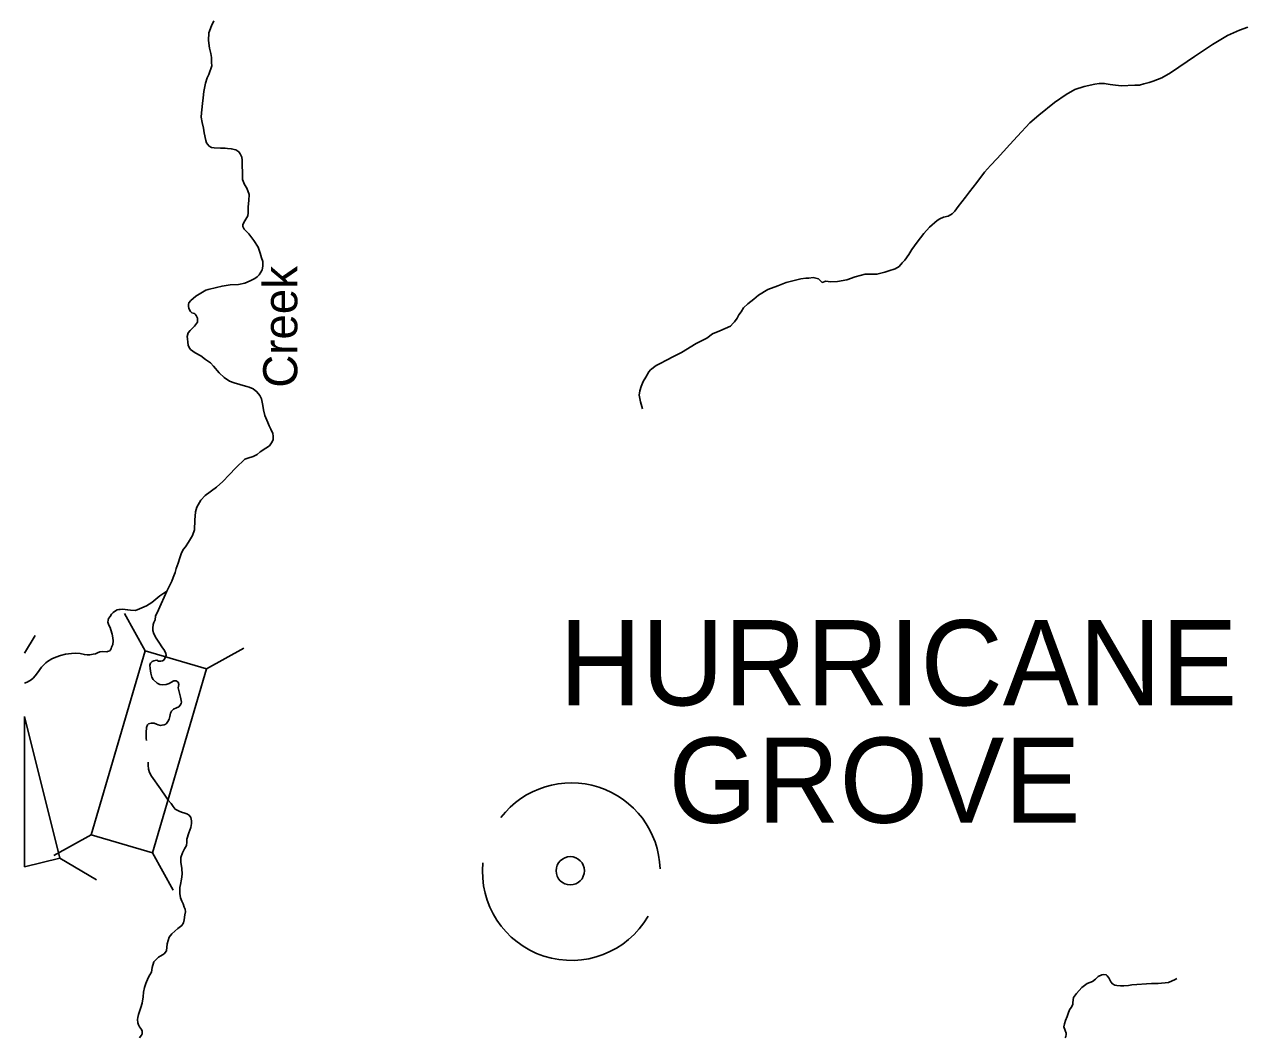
# Model space of a CAD drawing. Extents: x -492261 to -432772, y 1441225 to 1452922.
# Drawn here: x -461914.6 to -461726, y 1451913.8 to 1452070.7 of the extents above; entities that cross this region are included whole.
import ezdxf

# ---------------------------------------------------------------- set-up
doc = ezdxf.new("R2010")
doc.units = 0
doc.layers.add('Default', color=7, linetype='Continuous')

msp = doc.modelspace()

# ---------------------------------------------------------------- linework, layer by layer
at = {"layer": 'Default'}
for p, q in [((-461895.87, 1451973.72), (-461899.04, 1451979.51)), ((-461914.56, 1451973.33), (-461912.9, 1451976.1)), ((-461886.37, 1451970.94), (-461880.58, 1451974.11)), ((-461914.56, 1451963.53), (-461914.56, 1451940.25)), ((-461909.05, 1451941.63), (-461914.56, 1451963.53)), ((-461904.21, 1451945.22), (-461910, 1451942.05)), ((-461914.56, 1451940.25), (-461909.05, 1451941.63)), ((-461909.05, 1451941.63), (-461903.39, 1451938.24)), ((-461894.71, 1451942.44), (-461891.54, 1451936.65))]:
    msp.add_line(p, q, dxfattribs=at)
for points in [[(-461885.25, 1452071.25), (-461885.62, 1452070.49), (-461886.01, 1452069.39), (-461886.08, 1452068.21), (-461885.92, 1452067.04), (-461885.72, 1452066.21), (-461885.62, 1452065.56), (-461885.59, 1452064.79), (-461885.53, 1452064.28), (-461886, 1452062.96), (-461886.25, 1452062.43), (-461886.54, 1452061.63), (-461886.79, 1452060.32), (-461886.91, 1452059.35), (-461886.98, 1452058.47), (-461887.1, 1452057.49), (-461887.17, 1452057.02), (-461887.19, 1452056.34), (-461887.04, 1452055.52), (-461886.86, 1452054.62), (-461886.73, 1452053.92), (-461886.65, 1452053.44), (-461886.6, 1452053.19), (-461886.5, 1452052.74), (-461886.37, 1452052.39), (-461886.22, 1452052.14), (-461885.94, 1452051.84), (-461885.62, 1452051.67), (-461885.19, 1452051.6), (-461884.2, 1452051.55), (-461883.47, 1452051.53), (-461883.12, 1452051.51), (-461882.55, 1452051.44), (-461881.85, 1452051.27), (-461881.35, 1452050.97), (-461881.15, 1452050.67), (-461880.92, 1452050.17), (-461880.87, 1452049.67), (-461880.84, 1452048.97), (-461880.81, 1452047.67), (-461880.78, 1452046.67), (-461880.5, 1452045.94), (-461880.12, 1452045.37), (-461879.77, 1452044.39), (-461879.84, 1452043.42), (-461879.93, 1452042.47), (-461879.93, 1452041.87), (-461879.95, 1452041.51), (-461880, 1452041.06), (-461880.42, 1452040.31), (-461880.74, 1452039.73), (-461880.74, 1452039.43), (-461880.54, 1452038.98), (-461879.81, 1452038.26), (-461879.03, 1452037.24), (-461878.4, 1452036.22), (-461878.05, 1452035.29), (-461877.84, 1452034.57), (-461877.67, 1452033.99), (-461877.64, 1452033.39), (-461877.71, 1452032.89), (-461877.76, 1452032.72), (-461877.96, 1452032.32), (-461878.23, 1452031.94), (-461878.53, 1452031.61), (-461878.9, 1452031.36)], [(-461725.21, 1452070.26), (-461726.53, 1452069.83), (-461728.38, 1452068.98), (-461730.69, 1452067.61), (-461733.49, 1452065.73), (-461734.63, 1452064.96), (-461737.18, 1452063.21), (-461738.53, 1452062.44), (-461739.89, 1452061.94), (-461740.49, 1452061.72), (-461741.33, 1452061.48), (-461742, 1452061.32), (-461742.73, 1452061.29), (-461744.84, 1452061.19), (-461746.1, 1452061.34), (-461746.56, 1452061.4), (-461747.45, 1452061.57), (-461748.26, 1452061.54), (-461748.89, 1452061.47), (-461750.58, 1452061.09), (-461752.02, 1452060.61), (-461753.37, 1452059.86), (-461755.14, 1452058.62), (-461757.6, 1452056.64), (-461758.99, 1452055.47), (-461760.89, 1452053.41), (-461762.08, 1452052.12), (-461764, 1452049.92), (-461765.08, 1452048.85), (-461765.96, 1452047.82), (-461767.18, 1452046.21), (-461768.31, 1452044.77), (-461768.93, 1452043.97), (-461770.08, 1452042.49), (-461770.57, 1452041.81), (-461770.99, 1452041.35), (-461771.59, 1452041), (-461772.34, 1452040.85), (-461772.92, 1452040.59), (-461773.32, 1452040.33), (-461774.5, 1452039.31), (-461775.36, 1452038.33), (-461776.41, 1452037), (-461777.22, 1452035.84), (-461777.67, 1452035.06), (-461778.32, 1452034.21), (-461778.74, 1452033.77), (-461779.19, 1452033.24), (-461779.79, 1452032.85), (-461780.81, 1452032.55), (-461781.4, 1452032.35), (-461782.63, 1452032.02), (-461784.45, 1452032.01), (-461786, 1452031.61), (-461787.29, 1452031.18), (-461788.75, 1452030.9), (-461789.82, 1452030.87), (-461790.53, 1452030.96), (-461791.12, 1452030.76), (-461791.69, 1452031.3), (-461792.51, 1452031.5), (-461793.18, 1452031.44), (-461793.62, 1452031.44), (-461794.39, 1452031.3), (-461796.69, 1452030.74), (-461797.94, 1452030.25), (-461799.5, 1452029.68), (-461800.94, 1452028.8), (-461801.68, 1452028.14), (-461802.62, 1452027.42), (-461803.26, 1452026.82), (-461803.65, 1452026.21), (-461804.02, 1452025.72), (-461804.28, 1452025.24), (-461804.65, 1452024.65), (-461804.88, 1452024.44), (-461805.31, 1452023.99), (-461806.92, 1452023.26), (-461808.08, 1452022.78), (-461808.95, 1452022.14), (-461810.62, 1452021.3), (-461812.88, 1452019.93), (-461814.19, 1452019.26), (-461815.11, 1452018.77), (-461816.27, 1452018.16), (-461816.77, 1452017.88), (-461817.66, 1452017.2), (-461817.95, 1452016.93), (-461818.4, 1452016.08), (-461818.81, 1452015.39), (-461819.11, 1452014.63), (-461819.31, 1452013.98), (-461819.41, 1452013.29)], [(-461878.9, 1452031.36), (-461879.2, 1452031.21), (-461879.6, 1452030.98), (-461880.42, 1452030.62), (-461881.42, 1452030.44), (-461882.69, 1452030.36), (-461883.96, 1452030.2), (-461884.83, 1452029.97), (-461886.13, 1452029.66), (-461886.45, 1452029.56), (-461888.04, 1452028.63), (-461888.79, 1452027.95), (-461889.09, 1452027.59), (-461889.16, 1452027.34), (-461889.18, 1452027.09), (-461889.13, 1452026.72), (-461888.85, 1452026.24), (-461888.63, 1452026.07), (-461888.25, 1452025.95), (-461888.1, 1452025.85), (-461887.95, 1452025.65), (-461887.78, 1452025.22), (-461887.77, 1452024.62), (-461888.22, 1452023.99), (-461888.57, 1452023.64), (-461888.91, 1452023.32), (-461889.21, 1452022.94), (-461889.36, 1452022.36), (-461889.31, 1452022.01), (-461889.25, 1452021.51), (-461889.23, 1452021.06), (-461889.07, 1452020.66), (-461888.85, 1452020.39), (-461888.1, 1452019.87), (-461887.27, 1452019.37), (-461886.52, 1452018.82), (-461885.77, 1452018.3), (-461885.27, 1452017.8), (-461884.41, 1452016.78), (-461883.66, 1452016.06), (-461882.81, 1452015.49), (-461882.11, 1452015.2), (-461881.23, 1452014.95), (-461880.69, 1452014.8), (-461880.11, 1452014.63), (-461879.79, 1452014.53), (-461879.14, 1452014.26), (-461878.56, 1452013.84), (-461878.11, 1452013.24), (-461877.88, 1452012.72), (-461877.65, 1452011.69), (-461877.55, 1452011.04), (-461877.34, 1452010.17), (-461876.89, 1452009.09), (-461876.66, 1452008.57), (-461876.43, 1452008.04), (-461876.13, 1452007.35), (-461876.05, 1452006.97), (-461876.08, 1452006.39), (-461876.3, 1452005.92), (-461876.62, 1452005.47), (-461877.17, 1452005.11), (-461878.06, 1452004.53), (-461878.51, 1452004.13), (-461879.16, 1452003.82), (-461879.98, 1452003.57), (-461880.45, 1452003.39), (-461881.84, 1452002.06), (-461882.88, 1452000.95), (-461883.85, 1451999.94), (-461884.84, 1451999.08), (-461886.58, 1451997.77), (-461887.25, 1451997.04), (-461887.87, 1451995.96), (-461888.09, 1451995.24), (-461888.19, 1451993.96), (-461888.25, 1451992.46), (-461888.55, 1451991.55), (-461889.14, 1451990.52), (-461889.61, 1451989.82), (-461889.91, 1451989.47), (-461890.23, 1451988.87), (-461890.5, 1451988.11), (-461890.77, 1451987.29), (-461891.04, 1451986.46), (-461891.24, 1451985.86), (-461891.51, 1451985.08), (-461891.73, 1451984.5), (-461891.98, 1451983.97), (-461892.5, 1451982.94), (-461893.78, 1451980.08), (-461894.25, 1451979.08), (-461894.34, 1451978.53), (-461894.52, 1451978.1), (-461894.61, 1451977.8), (-461894.69, 1451977.22), (-461894.68, 1451976.85), (-461894.53, 1451976.37), (-461894.15, 1451975.68), (-461893.65, 1451974.9), (-461893.27, 1451974.35)], [(-461819.41, 1452013.29), (-461819.19, 1452012.25), (-461818.9, 1452011.18)], [(-461914.56, 1451968.72), (-461914.13, 1451968.85), (-461913.51, 1451969.2), (-461913.21, 1451969.48), (-461912.89, 1451969.83), (-461912.54, 1451970.29), (-461911.9, 1451971.19), (-461911.55, 1451971.54), (-461911.25, 1451971.87), (-461910.95, 1451972.07), (-461910.33, 1451972.45), (-461909.68, 1451972.73), (-461908.96, 1451973.01), (-461908.21, 1451973.22), (-461907.27, 1451973.3), (-461906.69, 1451973.35), (-461905.94, 1451973.28), (-461905.27, 1451973.13), (-461904.82, 1451973.09), (-461904.42, 1451973.11), (-461903.92, 1451973.19), (-461903.57, 1451973.27), (-461903.45, 1451973.32), (-461903.25, 1451973.42), (-461902.9, 1451973.55), (-461902.5, 1451973.6), (-461901.8, 1451973.58), (-461901.68, 1451973.6), (-461901.33, 1451973.73), (-461901.26, 1451973.81), (-461901.13, 1451974.03), (-461901.06, 1451974.26), (-461900.89, 1451974.69), (-461900.79, 1451975.26), (-461900.87, 1451975.71), (-461900.99, 1451976.29), (-461901.15, 1451976.94), (-461901.27, 1451977.31), (-461901.5, 1451977.71), (-461901.65, 1451978.13), (-461901.6, 1451978.44), (-461901.53, 1451978.74), (-461901.28, 1451979.01), (-461901.06, 1451979.39), (-461900.79, 1451979.67), (-461900.61, 1451979.79), (-461900.17, 1451980.07), (-461899.92, 1451980.1), (-461899.72, 1451980.12), (-461899.37, 1451980.15), (-461898.97, 1451980.13), (-461898.57, 1451980.06), (-461898.14, 1451980.03), (-461897.42, 1451979.96), (-461897.1, 1451980.04), (-461895.65, 1451980.7), (-461894.81, 1451981.18), (-461893.61, 1451982.21), (-461892.97, 1451982.64), (-461892.5, 1451982.94)], [(-461893.27, 1451974.35), (-461892.87, 1451973.78), (-461892.64, 1451973.31), (-461892.59, 1451973.06), (-461892.72, 1451972.81), (-461892.94, 1451972.3), (-461893.19, 1451972.15), (-461893.44, 1451972.13), (-461893.79, 1451972.1), (-461894.06, 1451972.25), (-461894.31, 1451972.2), (-461894.54, 1451972.14), (-461894.76, 1451972.07), (-461895.06, 1451971.79), (-461895.13, 1451971.47), (-461895.1, 1451970.99), (-461895, 1451970.24), (-461894.85, 1451969.64), (-461894.62, 1451969.27), (-461893.99, 1451968.69), (-461893.59, 1451968.52), (-461893.12, 1451968.45), (-461892.59, 1451968.48), (-461892.15, 1451968.65), (-461891.87, 1451968.81), (-461891.42, 1451969.06), (-461891.08, 1451969.06), (-461890.75, 1451968.84), (-461890.67, 1451968.49), (-461890.75, 1451967.96), (-461890.41, 1451966.56), (-461890.26, 1451965.79), (-461890.31, 1451965.54), (-461890.46, 1451965.29), (-461890.66, 1451965.03), (-461891.03, 1451964.91), (-461891.5, 1451964.68), (-461891.8, 1451964.35), (-461891.92, 1451964.07), (-461892.07, 1451963.55), (-461892.17, 1451963.12), (-461892.37, 1451962.75), (-461892.56, 1451962.44), (-461892.66, 1451962.34), (-461892.94, 1451962.24), (-461893.24, 1451962.21), (-461893.48, 1451962.16), (-461893.86, 1451962.24), (-461894.11, 1451962.36), (-461894.48, 1451962.53), (-461894.91, 1451962.53), (-461895.33, 1451962.43), (-461895.51, 1451962.25), (-461895.65, 1451961.83), (-461895.7, 1451961.07), (-461895.69, 1451960.12), (-461895.64, 1451959.82)], [(-461895.41, 1451956.46), (-461895.42, 1451956.02), (-461895.35, 1451955.37), (-461895.19, 1451954.89), (-461894.87, 1451954.3), (-461893.51, 1451952.35), (-461892.63, 1451951.08), (-461892.28, 1451950.61), (-461891.85, 1451950.08), (-461891.55, 1451949.61), (-461891.2, 1451949.21), (-461890.62, 1451948.89), (-461890.25, 1451948.72), (-461889.72, 1451948.59), (-461889.42, 1451948.5), (-461889.07, 1451948.27), (-461888.82, 1451947.9), (-461888.67, 1451947.4), (-461888.69, 1451947), (-461888.79, 1451946.35), (-461889.11, 1451945.54), (-461889.4, 1451944.57), (-461889.4, 1451944.07), (-461889.47, 1451943.59), (-461889.77, 1451943.06), (-461890.11, 1451942.43), (-461890.33, 1451941.73), (-461890.36, 1451940.98), (-461890.2, 1451940.03), (-461890.12, 1451939.16), (-461890.22, 1451938.35), (-461890.39, 1451937.55), (-461890.48, 1451937.05), (-461890.51, 1451936.5), (-461890.5, 1451936.12), (-461890.4, 1451935.47), (-461890.2, 1451934.95), (-461890, 1451934.55), (-461889.82, 1451934.05), (-461889.69, 1451933.73), (-461889.64, 1451933.3), (-461889.71, 1451932.82)], [(-461889.71, 1451932.82), (-461889.83, 1451932.07), (-461889.91, 1451931.6), (-461890.2, 1451931.17), (-461890.8, 1451930.72), (-461891.74, 1451929.91), (-461892.17, 1451929.36), (-461892.46, 1451928.35), (-461892.55, 1451927.25), (-461892.93, 1451926.8), (-461893.45, 1451926.47), (-461893.8, 1451926.29), (-461894.54, 1451925.54), (-461894.76, 1451924.71), (-461894.88, 1451923.98), (-461895.13, 1451923.56), (-461895.38, 1451923.1), (-461895.77, 1451922.2), (-461895.99, 1451921.6), (-461896.11, 1451920.87), (-461896.18, 1451920.15), (-461896.35, 1451919.14), (-461896.55, 1451918.49), (-461896.77, 1451917.74), (-461896.87, 1451917.41), (-461896.99, 1451916.94), (-461897.04, 1451916.64), (-461896.99, 1451916.11), (-461896.89, 1451915.79), (-461896.73, 1451915.49), (-461896.41, 1451915.09), (-461896.33, 1451914.84), (-461896.31, 1451914.74), (-461896.33, 1451914.39), (-461896.45, 1451914.19), (-461896.63, 1451913.94), (-461896.73, 1451913.82)], [(-461736.22, 1451923), (-461736.49, 1451922.81), (-461737.51, 1451922.38), (-461739.13, 1451922.2), (-461740.12, 1451922.22), (-461743.17, 1451922), (-461743.72, 1451921.92), (-461744.44, 1451921.84), (-461744.96, 1451921.86), (-461745.49, 1451921.88), (-461745.81, 1451921.96), (-461746.19, 1451922.18), (-461746.46, 1451922.48), (-461746.54, 1451922.68), (-461746.77, 1451923.1), (-461747.02, 1451923.4), (-461747.14, 1451923.55), (-461747.54, 1451923.6), (-461747.82, 1451923.55), (-461748.39, 1451923.29), (-461748.49, 1451923.19), (-461748.79, 1451922.89), (-461749.28, 1451922.54), (-461750.08, 1451922.21), (-461750.93, 1451921.58), (-461751.74, 1451920.67), (-461752.19, 1451920.02), (-461752.34, 1451919.26), (-461752.33, 1451918.96), (-461752.58, 1451918.51), (-461752.83, 1451918.11), (-461753.03, 1451917.58), (-461753.17, 1451917.08), (-461753.44, 1451916.46), (-461753.62, 1451915.98), (-461753.69, 1451915.48), (-461753.51, 1451914.93), (-461753.36, 1451914.53), (-461753.36, 1451914.33), (-461753.41, 1451914), (-461753.5, 1451913.82)]]:
    msp.add_lwpolyline(points, dxfattribs=at)
msp.add_lwpolyline([(-461895.87, 1451973.72), (-461904.21, 1451945.22), (-461894.71, 1451942.44), (-461886.37, 1451970.94)], close=True, dxfattribs=at)
msp.add_circle((-461830.08, 1451939.66), 2.19, dxfattribs=at)
for start, end in [(1.7357, 142.3681), (174.2558, 329.8683)]:
    msp.add_arc((-461829.92, 1451939.53), 13.75, start, end, dxfattribs=at)

# ---------------------------------------------------------------- texts
msp.add_text('Creek', height=5.28, rotation=90, dxfattribs=at).set_placement((-461872.32, 1452014.46))
for s, p in [('HURRICANE', (-461831.79, 1451965.27)), ('GROVE', (-461814.89, 1451947.09))]:
    msp.add_text(s, height=13.2, dxfattribs=at).set_placement(p)

doc.saveas('drawing.dxf')
